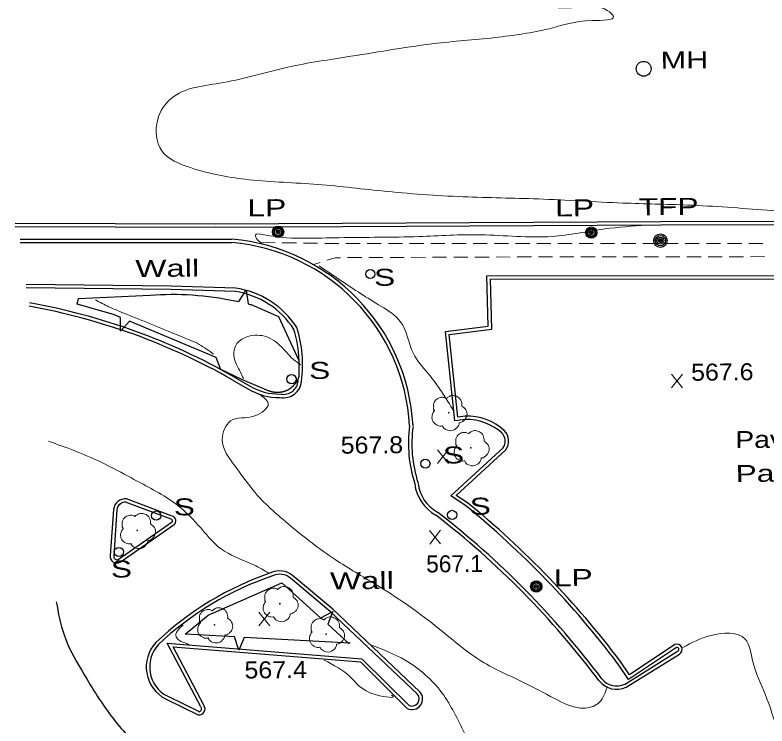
# Model space of a CAD drawing. Extents: x 2361708 to 2370558, y 6977955 to 6991887.
# Drawn here: x 2368404.6 to 2368617.4, y 6989255.9 to 6989457 of the extents above; entities that cross this region are included whole.
import ezdxf

# ---------------------------------------------------------------- set-up
doc = ezdxf.new("R2010")
doc.units = 0
doc.header["$LTSCALE"] = 1.9
for name, color, linetype, lineweight in [('13', 7, 'Continuous', 13), ('18', 7, 'Continuous', 25), ('2', 7, 'Continuous', 25), ('20', 7, 'Continuous', 25), ('21', 7, 'Continuous', 25), ('29', 7, 'Continuous', 13), ('31', 7, 'Continuous', 13), ('35', 7, 'Continuous', 13)]:
    doc.layers.add(name, color=color, linetype=linetype, lineweight=lineweight)

msp = doc.modelspace()

# ---------------------------------------------------------------- linework, layer by layer
at = {"layer": '13'}
for p, q in [((2368478.255, 6989392.631), (2368474.254, 6989392.683)), ((2368484.256, 6989392.558), (2368480.255, 6989392.61)), ((2368490.257, 6989392.475), (2368486.256, 6989392.528)), ((2368502.258, 6989392.399), (2368498.258, 6989392.401)), ((2368508.259, 6989392.396), (2368504.258, 6989392.398)), ((2368514.259, 6989392.393), (2368510.259, 6989392.395)), ((2368520.259, 6989392.391), (2368516.259, 6989392.392)), ((2368526.26, 6989392.388), (2368522.259, 6989392.39)), ((2368532.26, 6989392.385), (2368528.259, 6989392.387)), ((2368538.26, 6989392.382), (2368534.26, 6989392.384)), ((2368544.261, 6989392.379), (2368540.26, 6989392.381)), ((2368550.261, 6989392.376), (2368546.261, 6989392.378)), ((2368556.261, 6989392.373), (2368552.261, 6989392.375)), ((2368562.261, 6989392.37), (2368558.261, 6989392.372)), ((2368568.262, 6989392.368), (2368564.261, 6989392.369)), ((2368574.262, 6989392.365), (2368570.262, 6989392.367)), ((2368580.262, 6989392.372), (2368576.262, 6989392.364)), ((2368586.262, 6989392.379), (2368582.262, 6989392.371)), ((2368592.263, 6989392.376), (2368588.263, 6989392.378)), ((2368598.263, 6989392.373), (2368594.263, 6989392.375)), ((2368604.263, 6989392.37), (2368600.263, 6989392.372)), ((2368610.264, 6989392.367), (2368606.263, 6989392.369)), ((2368616.264, 6989392.365), (2368612.264, 6989392.366)), ((2368498.746, 6989388.396), (2368502.746, 6989388.414)), ((2368504.746, 6989388.423), (2368508.746, 6989388.441)), ((2368510.746, 6989388.45), (2368514.746, 6989388.468)), ((2368516.746, 6989388.477), (2368520.746, 6989388.495)), ((2368522.746, 6989388.504), (2368526.746, 6989388.522)), ((2368528.746, 6989388.532), (2368532.746, 6989388.539)), ((2368534.746, 6989388.549), (2368538.747, 6989388.557)), ((2368540.747, 6989388.566), (2368544.747, 6989388.584)), ((2368552.747, 6989388.6), (2368556.747, 6989388.608)), ((2368558.747, 6989388.607), (2368562.747, 6989388.615)), ((2368564.747, 6989388.614), (2368568.747, 6989388.622)), ((2368570.747, 6989388.621), (2368574.748, 6989388.629)), ((2368576.748, 6989388.628), (2368580.748, 6989388.636)), ((2368582.748, 6989388.635), (2368586.748, 6989388.643)), ((2368588.748, 6989388.643), (2368592.748, 6989388.651)), ((2368594.749, 6989388.65), (2368598.748, 6989388.658)), ((2368600.748, 6989388.657), (2368604.749, 6989388.665)), ((2368606.749, 6989388.664), (2368610.749, 6989388.672)), ((2368612.749, 6989388.671), (2368616.749, 6989388.679)), ((2368489.034, 6989386.463), (2368490.949, 6989387.052))]:
    msp.add_line(p, q, dxfattribs=at)
for points in [[(2368496.258, 6989392.402), (2368494.758, 6989392.408), (2368492.257, 6989392.444)], [(2368492.853, 6989387.65), (2368495.216, 6989388.382), (2368496.746, 6989388.387)], [(2368546.747, 6989388.593), (2368550.666, 6989388.6), (2368550.746, 6989388.601)]]:
    msp.add_lwpolyline(points, dxfattribs=at)
at = {"layer": '18'}
for p, q in [((2368468.943, 6989353.851), (2368462.514, 6989356.94)), ((2368493.163, 6989284.678), (2368499.215, 6989279.205)), ((2368499.424, 6989279.367), (2368469.467, 6989280.962))]:
    msp.add_line(p, q, dxfattribs=at)
for points in [[(2368434.494, 6989371.504), (2368432.516, 6989372.335), (2368422.207, 6989375.286), (2368422.543, 6989376.83), (2368442.815, 6989377.793), (2368444.323, 6989377.897), (2368445.823, 6989377.962), (2368447.322, 6989378.006), (2368448.842, 6989378.031), (2368450.353, 6989378.025), (2368451.853, 6989377.989), (2368453.363, 6989377.933), (2368454.864, 6989377.848), (2368456.365, 6989377.732), (2368457.867, 6989377.596), (2368459.359, 6989377.43), (2368460.86, 6989377.245), (2368462.353, 6989377.029), (2368463.835, 6989376.783), (2368465.318, 6989376.507), (2368466.791, 6989376.221), (2368467.913, 6989375.972)], [(2368467.923, 6989375.982), (2368470.032, 6989379.212), (2368470.619, 6989375.348)], [(2368470.609, 6989375.337), (2368471.2, 6989375.183), (2368471.441, 6989375.115), (2368479.154, 6989371.739), (2368484.973, 6989359.273), (2368484.896, 6989354.682), (2368484.867, 6989354.572), (2368484.828, 6989354.472), (2368484.789, 6989354.372), (2368484.75, 6989354.261), (2368484.711, 6989354.161), (2368484.662, 6989354.06), (2368484.623, 6989353.96), (2368484.574, 6989353.859), (2368484.525, 6989353.759), (2368484.476, 6989353.659), (2368484.427, 6989353.558), (2368484.368, 6989353.467), (2368484.309, 6989353.367), (2368484.26, 6989353.276), (2368484.201, 6989353.176), (2368484.141, 6989353.085), (2368484.072, 6989352.995), (2368484.013, 6989352.904), (2368483.944, 6989352.813), (2368483.885, 6989352.723), (2368483.816, 6989352.642), (2368483.747, 6989352.551), (2368483.667, 6989352.471), (2368483.598, 6989352.38), (2368483.529, 6989352.299), (2368483.45, 6989352.219), (2368483.371, 6989352.138), (2368483.291, 6989352.057), (2368483.212, 6989351.986), (2368483.133, 6989351.905), (2368483.053, 6989351.835), (2368482.964, 6989351.764), (2368482.885, 6989351.693), (2368482.795, 6989351.622), (2368482.706, 6989351.551), (2368482.627, 6989351.481), (2368482.537, 6989351.42), (2368482.438, 6989351.359), (2368482.349, 6989351.298), (2368482.259, 6989351.237), (2368482.16, 6989351.176), (2368482.07, 6989351.115), (2368481.971, 6989351.065), (2368481.871, 6989351.004), (2368481.782, 6989350.953), (2368481.682, 6989350.902), (2368481.583, 6989350.861), (2368481.483, 6989350.81), (2368481.383, 6989350.769), (2368481.274, 6989350.718), (2368481.174, 6989350.677), (2368481.075, 6989350.636), (2368480.965, 6989350.605), (2368480.865, 6989350.564), (2368480.756, 6989350.533), (2368480.646, 6989350.502), (2368480.546, 6989350.471), (2368480.437, 6989350.44), (2368480.327, 6989350.409), (2368480.217, 6989350.388), (2368480.117, 6989350.367), (2368480.007, 6989350.346), (2368479.898, 6989350.325), (2368479.788, 6989350.304), (2368479.678, 6989350.293), (2368479.568, 6989350.282), (2368479.459, 6989350.261), (2368479.349, 6989350.259), (2368479.238, 6989350.248), (2368479.128, 6989350.237), (2368479.019, 6989350.236), (2368478.898, 6989350.235), (2368478.788, 6989350.234), (2368478.678, 6989350.233), (2368478.568, 6989350.242), (2368478.458, 6989350.251), (2368478.348, 6989350.25), (2368478.238, 6989350.259), (2368478.128, 6989350.278), (2368478.018, 6989350.287), (2368477.908, 6989350.306), (2368477.797, 6989350.325), (2368477.687, 6989350.344), (2368477.577, 6989350.363), (2368477.477, 6989350.382), (2368477.367, 6989350.411), (2368477.256, 6989350.44), (2368477.146, 6989350.469), (2368477.046, 6989350.498), (2368476.935, 6989350.526), (2368476.835, 6989350.556), (2368476.725, 6989350.594), (2368476.624, 6989350.633), (2368476.574, 6989350.653), (2368468.943, 6989353.851)], [(2368437.044, 6989370.437), (2368434.421, 6989367.592), (2368434.494, 6989371.504)], [(2368462.774, 6989356.942), (2368461.533, 6989360.15), (2368437.044, 6989370.437)], [(2368466.706, 6989281.106), (2368452.768, 6989281.853), (2368459.227, 6989287.245), (2368480.151, 6989296.444), (2368491.105, 6989286.538)], [(2368491.115, 6989286.528), (2368494.528, 6989288.341), (2368493.163, 6989284.678)], [(2368469.467, 6989280.962), (2368467.951, 6989277.408), (2368466.696, 6989281.116)]]:
    msp.add_lwpolyline(points, dxfattribs=at)
at = {"layer": '2'}
for p, q in [((2368406.071, 6989392.644), (2368465.954, 6989392.654)), ((2368406.072, 6989393.604), (2368465.955, 6989393.614)), ((2368466.083, 6989353.883), (2368470.487, 6989351.335)), ((2368466.565, 6989354.718), (2368470.969, 6989352.17)), ((2368449.1, 6989315.29), (2368436.203, 6989320.147)), ((2368448.758, 6989314.387), (2368435.861, 6989319.244)), ((2368432.481, 6989317.171), (2368431.585, 6989304.132)), ((2368433.442, 6989317.111), (2368432.546, 6989304.071)), ((2368433.836, 6989303.014), (2368449.085, 6989313.7)), ((2368434.383, 6989302.229), (2368449.632, 6989312.915)), ((2368577.059, 6989267.675), (2368592.1, 6989277.059)), ((2368577.567, 6989266.86), (2368592.608, 6989276.244)), ((2368447.633, 6989264.423), (2368456.887, 6989259.941)), ((2368447.212, 6989263.559), (2368456.465, 6989259.077))]:
    msp.add_line(p, q, dxfattribs=at)
for points in [[(2368782.79, 6989398.83), (2368685.726, 6989398.816), (2368587.383, 6989398.57), (2368461.214, 6989397.859), (2368404.62, 6989398.04)], [(2368782.79, 6989397.87), (2368685.725, 6989397.856), (2368587.383, 6989397.61), (2368461.213, 6989396.899), (2368404.619, 6989397.08)], [(2368532.133, 6989342.622), (2368529.067, 6989342.192), (2368526.456, 6989367.489), (2368538.553, 6989369.004), (2368538.157, 6989383.251), (2368655.792, 6989383.39), (2368646.451, 6989369.711)], [(2368532.004, 6989343.57), (2368529.917, 6989343.28), (2368527.505, 6989366.649), (2368539.541, 6989368.163), (2368539.146, 6989382.29), (2368653.97, 6989382.433), (2368645.656, 6989370.253)], [(2368466.976, 6989378.803), (2368448.759, 6989379.38), (2368407.813, 6989379.85)], [(2368467.007, 6989379.763), (2368448.78, 6989380.34), (2368407.814, 6989380.81)], [(2368532.135, 6989318.27), (2368527.929, 6989320.991), (2368542.819, 6989334.713)], [(2368532.658, 6989319.075), (2368529.488, 6989321.126), (2368543.466, 6989334.009)], [(2368519.165, 6989265.624), (2368494.542, 6989288.971), (2368483.161, 6989298.504)], [(2368518.502, 6989264.928), (2368493.899, 6989288.255), (2368482.548, 6989297.767)], [(2368457.203, 6989261.364), (2368447.692, 6989279.365), (2368502.786, 6989274.949), (2368516.264, 6989261.596)], [(2368458.049, 6989261.812), (2368449.352, 6989278.27), (2368502.355, 6989274.025), (2368515.591, 6989260.91)], [(2368591.84, 6989278.147), (2368578.265, 6989269.087), (2368575.122, 6989273.647)], [(2368591.302, 6989278.942), (2368578.523, 6989270.41), (2368575.917, 6989274.195)]]:
    msp.add_lwpolyline(points, dxfattribs=at)
for centre, radius, start, end in [((2368461.233, 6989337.713), 55.144, 3.20983, 85.08869), ((2368461.233, 6989337.713), 56.103, 3.20983, 85.08869), ((2368463.521, 6989355.247), 24.763, 32.68143, 81.90814), ((2368463.521, 6989355.247), 23.803, 32.68143, 81.90814), ((2368376.844, 6989196.67), 181.735, 60.41951, 79.88821), ((2368376.844, 6989196.67), 180.775, 60.41951, 79.88821), ((2368451.709, 6989358.125), 33.339, 1.97976, 17.81439), ((2368451.709, 6989358.125), 34.299, 352.16626, 17.81439), ((2368479.178, 6989365.326), 15.51, 238.15405, 271.61316), ((2368480.6, 6989353.878), 5.107, 259.18428, 355.18741), ((2368480.6, 6989353.878), 4.147, 259.18428, 355.18741), ((2368451.709, 6989358.125), 33.339, 352.16626, 352.34629), ((2368479.178, 6989365.326), 16.47, 238.15405, 271.61316), ((2368532.485, 6989327.888), 15.69, 47.5531, 91.75486), ((2368532.485, 6989327.888), 14.73, 47.5531, 91.75486), ((2368552.8, 6989335.787), 36.853, 172.18036, 197.97518), ((2368552.8, 6989335.787), 35.893, 172.18036, 197.97518), ((2368540.194, 6989336.516), 4.122, 322.5341, 45.67939), ((2368540.194, 6989336.516), 3.162, 322.5341, 45.67939), ((2368529.279, 6989325.755), 11.61, 186.63671, 241.11584), ((2368529.279, 6989325.755), 10.65, 186.63671, 241.11584), ((2368435.869, 6989316.75), 3.413, 84.39631, 172.90979), ((2368435.869, 6989316.75), 2.453, 84.39631, 172.90979), ((2368368.86, 6989117.905), 258.461, 37.04599, 50.84661), ((2368368.86, 6989117.905), 259.421, 37.04599, 50.84661), ((2368373.063, 6989120.858), 246.177, 36.90291, 52.28123), ((2368373.063, 6989120.858), 247.137, 36.90291, 52.28123), ((2368448.796, 6989313.974), 0.389, 308.27726, 77.0279), ((2368448.796, 6989313.974), 1.349, 308.27726, 77.0279), ((2368433.437, 6989303.848), 1.873, 171.27014, 300.3111), ((2368433.437, 6989303.848), 0.913, 171.27014, 300.3111), ((2368505.998, 6989214.529), 89.534, 108.78048, 133.4358), ((2368479.531, 6989294.09), 5.714, 50.56288, 114.36437), ((2368479.531, 6989294.09), 4.754, 50.56288, 114.36437), ((2368505.998, 6989214.529), 88.574, 108.78048, 133.4358), ((2368452.01, 6989272.624), 10.256, 137.57025, 242.10917), ((2368452.01, 6989272.624), 9.296, 137.57025, 242.10917), ((2368591.934, 6989277.581), 1.497, 296.77066, 114.88705), ((2368591.934, 6989277.581), 0.537, 296.77066, 114.88705), ((2368574.916, 6989272.706), 6.418, 218.87494, 294.39316), ((2368574.916, 6989272.706), 5.458, 218.87494, 294.39316), ((2368516.963, 6989263.583), 3.004, 242.82139, 42.82224), ((2368516.963, 6989263.583), 2.044, 242.82139, 42.82224), ((2368456.652, 6989260.794), 1.727, 263.79591, 36.08394), ((2368456.652, 6989260.794), 0.767, 263.79591, 36.08394)]:
    msp.add_arc(centre, radius, start, end, dxfattribs=at)
at = {"layer": '20'}
for centre, radius in [((2368582.522, 6989441.826), 2.1), ((2368479.066, 6989395.689), 1.6), ((2368479.066, 6989395.689), 1.3), ((2368479.066, 6989395.689), 1), ((2368567.672, 6989395.472), 1.6), ((2368567.672, 6989395.472), 1.3), ((2368567.672, 6989395.472), 1), ((2368479.066, 6989395.689), 0.539), ((2368479.066, 6989395.689), 0.192), ((2368567.672, 6989395.472), 0.539), ((2368567.672, 6989395.472), 0.192), ((2368587.245, 6989393.208), 1.9), ((2368587.245, 6989393.208), 1.442), ((2368587.245, 6989393.208), 0.973), ((2368587.245, 6989393.208), 0.539), ((2368587.245, 6989393.208), 0.192), ((2368552.124, 6989295.379), 1.6), ((2368552.124, 6989295.379), 1.3), ((2368552.124, 6989295.379), 1), ((2368552.124, 6989295.379), 0.539), ((2368552.124, 6989295.379), 0.192)]:
    msp.add_circle(centre, radius, dxfattribs=at)
at = {"layer": '21'}
for centre in [(2368505.171, 6989383.767), (2368482.872, 6989354.033), (2368520.752, 6989330.123), (2368444.568, 6989315.437), (2368528.32, 6989315.624), (2368434.005, 6989305.146)]:
    msp.add_circle(centre, 1.3, dxfattribs=at)
at = {"layer": '29'}
for centre in [(2368527.345, 6989344.546), (2368533.61, 6989334.615), (2368439.218, 6989311.196), (2368479.567, 6989290.519), (2368461.063, 6989284.502), (2368492.679, 6989281.923)]:
    msp.add_circle(centre, 0.1, dxfattribs=at)
for points in [[(2368523.379, 6989345.118), (2368523.399, 6989345.128), (2368523.318, 6989345.198), (2368523.082, 6989345.826), (2368523.12, 6989347.106), (2368524.008, 6989348.404), (2368525.314, 6989348.887), (2368526.435, 6989348.697), (2368526.666, 6989348.57), (2368526.737, 6989348.57), (2368526.786, 6989348.611), (2368527.133, 6989348.904), (2368527.999, 6989349.353), (2368529.21, 6989349.284), (2368530.326, 6989348.694), (2368531.059, 6989347.271), (2368531.067, 6989346.411)], [(2368531.057, 6989346.431), (2368532.198, 6989345.372), (2368532.482, 6989343.785), (2368531.775, 6989342.458), (2368531.12, 6989341.912), (2368530.452, 6989341.695), (2368530.302, 6989341.684), (2368530.284, 6989341.574), (2368529.962, 6989340.67), (2368528.423, 6989339.506), (2368526.53, 6989339.788), (2368525.631, 6989340.729), (2368525.56, 6989340.859), (2368525.44, 6989340.837), (2368524.229, 6989340.956), (2368522.96, 6989341.954), (2368522.614, 6989343.591), (2368522.984, 6989344.615), (2368523.31, 6989345.058), (2368523.379, 6989345.108)], [(2368529.644, 6989335.187), (2368529.664, 6989335.198), (2368529.583, 6989335.267), (2368529.347, 6989335.895), (2368529.385, 6989337.175), (2368530.273, 6989338.474), (2368531.578, 6989338.956), (2368532.7, 6989338.767), (2368532.932, 6989338.639), (2368533.001, 6989338.639), (2368533.051, 6989338.68), (2368533.398, 6989338.973), (2368534.264, 6989339.421), (2368535.475, 6989339.353), (2368536.59, 6989338.764), (2368537.324, 6989337.341), (2368537.332, 6989336.481)], [(2368537.322, 6989336.5), (2368538.462, 6989335.441), (2368538.747, 6989333.854), (2368538.04, 6989332.527), (2368537.385, 6989331.981), (2368536.717, 6989331.765), (2368536.567, 6989331.753), (2368536.548, 6989331.643), (2368536.227, 6989330.74), (2368534.688, 6989329.575), (2368532.795, 6989329.857), (2368531.896, 6989330.799), (2368531.825, 6989330.928), (2368531.705, 6989330.907), (2368530.494, 6989331.025), (2368529.224, 6989332.023), (2368528.878, 6989333.66), (2368529.249, 6989334.684), (2368529.575, 6989335.127), (2368529.644, 6989335.177)], [(2368435.252, 6989311.768), (2368435.272, 6989311.778), (2368435.192, 6989311.847), (2368434.956, 6989312.475), (2368434.993, 6989313.756), (2368435.881, 6989315.054), (2368437.187, 6989315.536), (2368438.309, 6989315.347), (2368438.54, 6989315.219), (2368438.61, 6989315.22), (2368438.659, 6989315.26), (2368439.006, 6989315.554), (2368439.872, 6989316.002), (2368441.083, 6989315.934), (2368442.198, 6989315.344), (2368442.933, 6989313.921), (2368442.941, 6989313.061)], [(2368442.93, 6989313.081), (2368444.07, 6989312.022), (2368444.356, 6989310.434), (2368443.649, 6989309.107), (2368442.993, 6989308.561), (2368442.325, 6989308.345), (2368442.175, 6989308.334), (2368442.156, 6989308.224), (2368441.835, 6989307.32), (2368440.296, 6989306.155), (2368438.403, 6989306.438), (2368437.505, 6989307.379), (2368437.433, 6989307.508), (2368437.314, 6989307.487), (2368436.102, 6989307.606), (2368434.832, 6989308.604), (2368434.487, 6989310.24), (2368434.857, 6989311.264), (2368435.183, 6989311.707), (2368435.252, 6989311.758)], [(2368475.601, 6989291.091), (2368475.621, 6989291.101), (2368475.54, 6989291.171), (2368475.304, 6989291.798), (2368475.342, 6989293.078), (2368476.23, 6989294.377), (2368477.536, 6989294.859), (2368478.657, 6989294.67), (2368478.888, 6989294.542), (2368478.959, 6989294.543), (2368479.008, 6989294.584), (2368479.355, 6989294.877), (2368480.221, 6989295.325), (2368481.432, 6989295.256), (2368482.547, 6989294.667), (2368483.281, 6989293.244), (2368483.289, 6989292.384)], [(2368483.279, 6989292.404), (2368484.419, 6989291.345), (2368484.704, 6989289.757), (2368483.997, 6989288.431), (2368483.342, 6989287.884), (2368482.674, 6989287.668), (2368482.524, 6989287.657), (2368482.505, 6989287.546), (2368482.184, 6989286.643), (2368480.645, 6989285.479), (2368478.752, 6989285.761), (2368477.853, 6989286.702), (2368477.782, 6989286.831), (2368477.662, 6989286.81), (2368476.451, 6989286.929), (2368475.181, 6989287.927), (2368474.836, 6989289.563), (2368475.206, 6989290.587), (2368475.532, 6989291.03), (2368475.601, 6989291.081)], [(2368457.098, 6989285.075), (2368457.117, 6989285.085), (2368457.037, 6989285.154), (2368456.801, 6989285.782), (2368456.838, 6989287.062), (2368457.726, 6989288.361), (2368459.032, 6989288.843), (2368460.154, 6989288.654), (2368460.385, 6989288.526), (2368460.455, 6989288.526), (2368460.504, 6989288.567), (2368460.852, 6989288.86), (2368461.717, 6989289.308), (2368462.928, 6989289.24), (2368464.044, 6989288.651), (2368464.777, 6989287.228), (2368464.786, 6989286.368)], [(2368464.776, 6989286.388), (2368465.916, 6989285.329), (2368466.201, 6989283.741), (2368465.493, 6989282.414), (2368464.839, 6989281.868), (2368464.17, 6989281.652), (2368464.021, 6989281.64), (2368464.002, 6989281.53), (2368463.68, 6989280.627), (2368462.141, 6989279.462), (2368460.249, 6989279.744), (2368459.349, 6989280.686), (2368459.278, 6989280.815), (2368459.158, 6989280.794), (2368457.947, 6989280.912), (2368456.677, 6989281.91), (2368456.332, 6989283.547), (2368456.702, 6989284.571), (2368457.028, 6989285.014), (2368457.098, 6989285.065)], [(2368488.714, 6989282.495), (2368488.733, 6989282.505), (2368488.653, 6989282.575), (2368488.417, 6989283.202), (2368488.455, 6989284.483), (2368489.343, 6989285.781), (2368490.648, 6989286.264), (2368491.77, 6989286.075), (2368492.001, 6989285.947), (2368492.071, 6989285.947), (2368492.121, 6989285.988), (2368492.468, 6989286.281), (2368493.333, 6989286.729), (2368494.544, 6989286.661), (2368495.66, 6989286.072), (2368496.394, 6989284.649), (2368496.402, 6989283.788)], [(2368496.392, 6989283.808), (2368497.532, 6989282.749), (2368497.817, 6989281.162), (2368497.109, 6989279.835), (2368496.455, 6989279.289), (2368495.787, 6989279.072), (2368495.637, 6989279.061), (2368495.618, 6989278.951), (2368495.296, 6989278.048), (2368493.757, 6989276.883), (2368491.865, 6989277.165), (2368490.965, 6989278.107), (2368490.895, 6989278.236), (2368490.774, 6989278.215), (2368489.563, 6989278.333), (2368488.294, 6989279.331), (2368487.948, 6989280.968), (2368488.318, 6989281.991), (2368488.645, 6989282.435), (2368488.714, 6989282.485)]]:
    msp.add_spline(points, degree=3, dxfattribs=at)
at = {"layer": '31'}
for p, q in [((2368593.511, 6989351.606), (2368590.394, 6989355.456)), ((2368590.431, 6989351.577), (2368593.474, 6989355.486)), ((2368527.272, 6989330.175), (2368524.155, 6989334.025)), ((2368524.192, 6989330.146), (2368527.235, 6989334.054)), ((2368525.048, 6989307.402), (2368521.932, 6989311.252)), ((2368521.969, 6989307.373), (2368525.012, 6989311.282)), ((2368476.716, 6989284.251), (2368473.6, 6989288.102)), ((2368473.637, 6989284.222), (2368476.68, 6989288.131))]:
    msp.add_line(p, q, dxfattribs=at)
at = {"layer": '31', "lineweight": 25}
msp.add_spline([(2368416.279, 6989291.056), (2368418.478, 6989281.687), (2368423.392, 6989271.803), (2368431.938, 6989258.604), (2368441.631, 6989248.926), (2368452.575, 6989243.34), (2368466.269, 6989234.599), (2368470.4, 6989231.238)], degree=3, dxfattribs=at)
at = {"layer": '35'}
for points in [[(2368550.932, 6989459.466), (2368565.765, 6989459.237), (2368572.224, 6989458.349), (2368573.94, 6989456.665), (2368567.911, 6989455.467), (2368556.511, 6989453.359), (2368541.474, 6989450.766), (2368524.12, 6989449.05), (2368499.664, 6989445.347), (2368481.783, 6989442.267), (2368463.523, 6989437.923), (2368448.775, 6989433.403), (2368444.982, 6989427.436), (2368446.136, 6989418.656), (2368454.232, 6989413.873), (2368469.684, 6989410.56), (2368489.078, 6989409.195), (2368508.457, 6989407.269), (2368531.454, 6989405.618), (2368552.711, 6989405), (2368576.663, 6989403.848), (2368594.949, 6989403.272), (2368617.494, 6989401.797), (2368637.179, 6989400.354), (2368652.863, 6989399.993), (2368671.805, 6989399.884), (2368685.967, 6989398.688)], [(2368583.323, 6989397.581), (2368571.522, 6989396.519), (2368556.581, 6989394.407), (2368536.416, 6989394.855), (2368518.9, 6989394.378), (2368496.262, 6989394.033), (2368486.874, 6989393.873), (2368474.753, 6989394.928), (2368472.713, 6989394.848), (2368473.227, 6989393.483), (2368474.577, 6989392.406)], [(2368490.688, 6989386.079), (2368496.848, 6989381.897), (2368508.178, 6989374.645), (2368513.709, 6989370.287), (2368517.335, 6989361.271), (2368521.549, 6989355.581), (2368525.298, 6989350.497), (2368528.841, 6989344.93)], [(2368427.406, 6989376.436), (2368431.135, 6989374.532), (2368435.372, 6989372.712), (2368438.745, 6989371.364), (2368445.833, 6989368.471), (2368451.406, 6989366.154), (2368456.758, 6989363.835), (2368460.794, 6989361.113)], [(2368485.423, 6989358.118), (2368482.966, 6989359.995), (2368480.632, 6989362.492), (2368475.888, 6989365.987), (2368470.527, 6989366.076), (2368467.416, 6989364.077), (2368466.558, 6989360.738), (2368467.282, 6989358.185), (2368468.393, 6989355.985), (2368469.23, 6989354.253)], [(2368473.673, 6989349.786), (2368476.258, 6989347.12), (2368472.491, 6989343.664), (2368465.604, 6989342.208), (2368463.274, 6989336.956), (2368466.815, 6989329.529), (2368471.981, 6989322.618), (2368482.577, 6989312.538), (2368495.179, 6989303.038), (2368506.847, 6989295.879), (2368523.529, 6989284.287), (2368537.369, 6989273.808), (2368549.456, 6989267.793), (2368558.422, 6989263.118), (2368565.552, 6989260.966), (2368569.61, 6989262.275), (2368572.01, 6989266.467), (2368572.107, 6989266.788)], [(2368414.076, 6989336.478), (2368425.137, 6989332.282), (2368440.14, 6989324.685), (2368451.538, 6989317.623), (2368457.02, 6989312.125), (2368462.133, 6989306.624), (2368469.993, 6989302.418), (2368472.192, 6989301.459), (2368476.464, 6989299.14)], [(2368452.153, 6989284.517), (2368450.215, 6989281.129), (2368451.054, 6989280.167), (2368453.223, 6989279.237), (2368453.885, 6989278.974)], [(2368593.6, 6989278.144), (2368601.558, 6989281.539), (2368611.209, 6989280.501), (2368613.421, 6989274.032), (2368616.887, 6989264.965), (2368620.581, 6989254.059), (2368627.209, 6989238.592), (2368632.924, 6989229.615)], [(2368505.239, 6989278.893), (2368515.021, 6989274.525), (2368525.439, 6989265.294), (2368531.818, 6989253.894), (2368536.781, 6989244.121), (2368543.081, 6989230.47), (2368553.209, 6989212.956), (2368564.883, 6989198.946), (2368569.727, 6989191.102), (2368569.839, 6989190.903)], [(2368492.129, 6989274.537), (2368499.152, 6989270.134), (2368506.934, 6989264.718), (2368511.527, 6989264.362), (2368511.025, 6989264.647)]]:
    msp.add_spline(points, degree=3, dxfattribs=at)

# ---------------------------------------------------------------- texts
at = {"layer": '18', "width": 1.45}
for p in [(2368438.686, 6989382.904), (2368493.77, 6989294.554)]:
    msp.add_text('Wall', height=4.8, rotation=0.545, dxfattribs=at).set_placement(p)
at = {"layer": '2'}
for s, width, p in [('Paved', 1.25, (2368608.454, 6989334.507)), ('Parking', 1.4, (2368608.546, 6989324.908))]:
    msp.add_text(s, height=4.8, rotation=0.545, dxfattribs=dict(at, width=width)).set_placement(p)
at = {"layer": '20'}
for s, width, p in [('  MH', 1.35, (2368582.522, 6989441.826)), ('  LP', 1.4, (2368465.414, 6989400.019)), ('  LP', 1.4, (2368552.498, 6989399.998)), ('  TFP', 1.4, (2368576.107, 6989400.313)), ('  LP', 1.4, (2368552.124, 6989295.379))]:
    msp.add_text(s, height=4.8, rotation=0.545, dxfattribs=dict(at, width=width)).set_placement(p)
at = {"layer": '21', "width": 1.4}
for p in [(2368501.233, 6989380.369), (2368482.863, 6989354.023), (2368520.742, 6989330.112), (2368444.558, 6989315.426), (2368528.31, 6989315.614), (2368426.755, 6989297.856)]:
    msp.add_text('  S', height=4.8, rotation=0.545, dxfattribs=at).set_placement(p)
at = {"layer": '31', "width": 1.1}
for s, p in [('567.6', (2368595.953, 6989353.569)), ('567.8', (2368496.794, 6989332.944)), ('567.4', (2368469.568, 6989269.352))]:
    msp.add_text(s, height=4.8, rotation=0.545, dxfattribs=at).set_placement(p)
at = {"layer": '31'}
msp.add_text('567.1', height=4.8, rotation=0.545, dxfattribs=at).set_placement((2368520.985, 6989299.343))

doc.saveas('drawing.dxf')
